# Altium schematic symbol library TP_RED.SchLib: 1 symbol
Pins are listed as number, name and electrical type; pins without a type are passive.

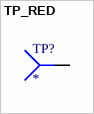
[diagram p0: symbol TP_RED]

## TP_RED
designator TP?
RF EMI Absorbing Sheet - Polyurethane Foam 24.000 (609.60mm) X 24.000 (609.60mm) X 0.252 (6.40mm); MF: Aeroflex; MP: 5010
footprint TP_RED
pins: 1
